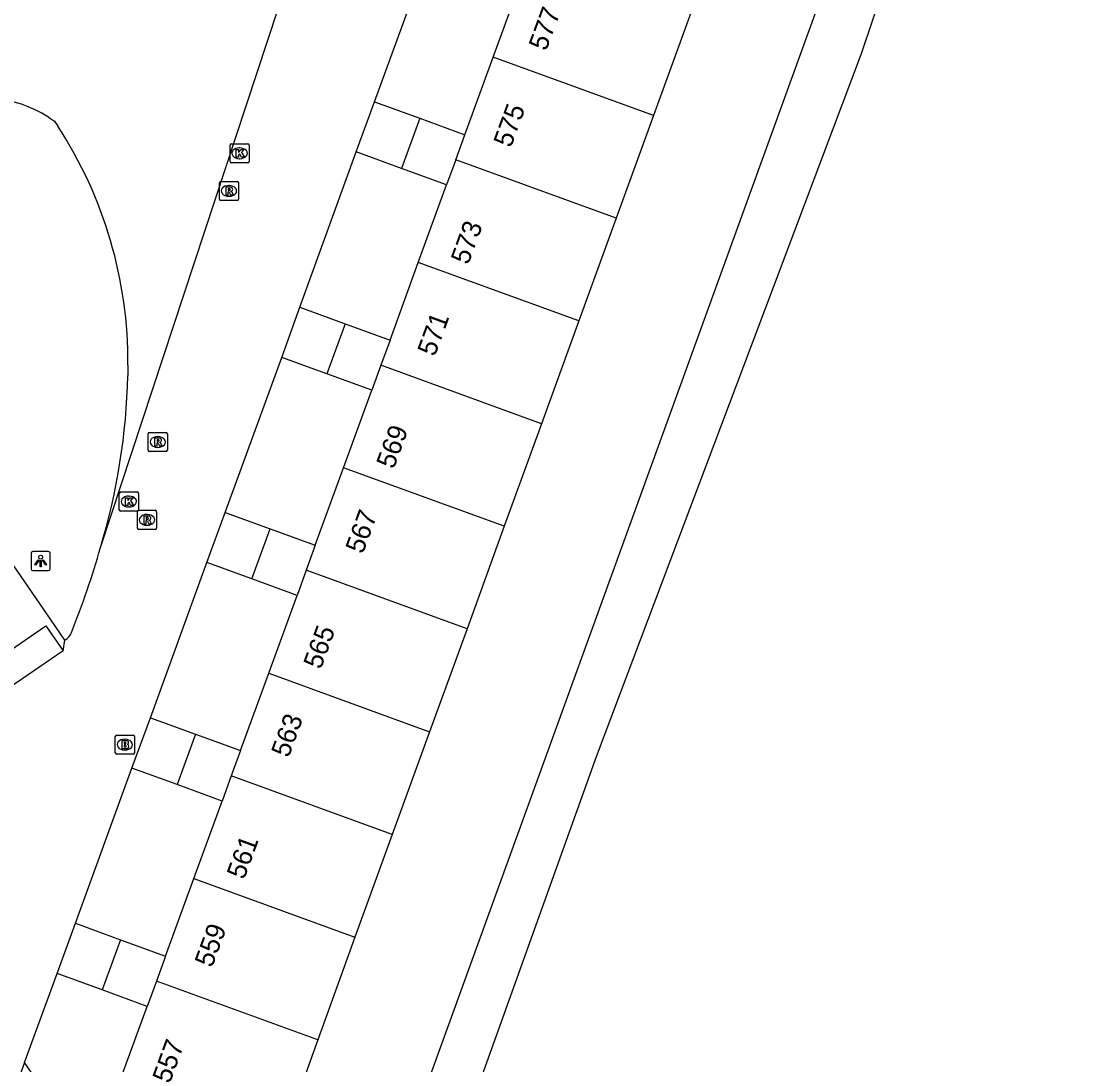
# Model space of a CAD drawing. Extents: x 155275 to 156263, y 382654 to 383635.
# Drawn here: x 155787.6 to 155842.7, y 383458.9 to 383513.4 of the extents above; entities that cross this region are included whole.
import ezdxf

# ---------------------------------------------------------------- set-up
doc = ezdxf.new("R2010")
doc.units = 0
for name, color, linetype in [('IMGEO_Brandkraan', 7, 'Continuous'), ('IMGEO_Erf', 7, 'Continuous'), ('IMGEO_Groenvoorziening', 7, 'Continuous'), ('IMGEO_Kolk', 7, 'Continuous'), ('IMGEO_Lichtpunt', 7, 'Continuous'), ('IMGEO_Meer_plas_ven_vijver', 7, 'Continuous'), ('IMGEO_Pand', 7, 'Continuous'), ('IMGEO_Pand_nummerreeks', 7, 'Continuous'), ('IMGEO_Rijbaan_lokaal_open', 7, 'Continuous'), ('IMGEO_Rioolput', 7, 'Continuous')]:
    doc.layers.add(name, color=color, linetype=linetype)

msp = doc.modelspace()

# ---------------------------------------------------------------- linework, layer by layer
at = {"layer": 'IMGEO_Brandkraan'}
for p, q in [((155792.473, 383475.2), (155792.473, 383476.052)), ((155792.548, 383476.126), (155793.4, 383476.126)), ((155793.474, 383476.052), (155793.474, 383475.2)), ((155792.961, 383475.906), (155792.986, 383475.906)), ((155793.4, 383475.126), (155792.548, 383475.126)), ((155792.984, 383475.346), (155792.959, 383475.346))]:
    msp.add_line(p, q, dxfattribs=at)
for points in [[(155792.473, 383475.2), (155792.473, 383476.052)], [(155792.548, 383476.126), (155793.4, 383476.126)], [(155793.474, 383476.052), (155793.474, 383475.2)], [(155792.821, 383475.826), (155792.821, 383475.426), (155793.034, 383475.426)], [(155793.052, 383475.826), (155792.821, 383475.826)], [(155793, 383475.745), (155792.946, 383475.745), (155792.946, 383475.669)], [(155792.946, 383475.669), (155792.999, 383475.669)], [(155793.008, 383475.593), (155792.946, 383475.593), (155792.946, 383475.512)], [(155792.946, 383475.512), (155793.008, 383475.512)], [(155793.4, 383475.126), (155792.548, 383475.126)]]:
    msp.add_lwpolyline(points, dxfattribs=at)
for centre, radius, start, end in [((155792.55, 383476.05), 0.0765, 91.552, 178.448), ((155792.55, 383476.05), 0.0765, 91.552, 178.448), ((155793.398, 383476.05), 0.0765, 1.552, 88.448), ((155793.398, 383476.05), 0.0765, 1.552, 88.448), ((155793.001, 383475.707), 0.0379, 267.8285, 90.9355), ((155793.009, 383475.552), 0.0404, 269.8759, 90.5077), ((155793.056, 383475.681), 0.145, 59.4692, 91.5367), ((155793.081, 383475.728), 0.0922, 285.5137, 58.1501), ((155793.086, 383475.536), 0.105, 301.3115, 78.989), ((155792.55, 383475.202), 0.0765, 181.552, 268.448), ((155792.55, 383475.202), 0.0765, 181.552, 268.448), ((155793.04, 383475.677), 0.251, 268.6676, 293.5347), ((155793.398, 383475.202), 0.0765, 271.552, 358.448), ((155793.398, 383475.202), 0.0765, 271.552, 358.448)]:
    msp.add_arc(centre, radius, start, end, dxfattribs=at)
for centre, major_axis, ratio, start_param, end_param in [((155792.96, 383475.626), (-0.387, 0.002), 0.722429, 4.712389, 7.853982), ((155792.985, 383475.626), (-0.39, 0.002), 0.717154, 1.570796, 4.712389)]:
    msp.add_ellipse(centre, major_axis=major_axis, ratio=ratio, start_param=start_param, end_param=end_param, dxfattribs=at)
at = {"layer": 'IMGEO_Erf'}
msp.add_lwpolyline([(155834.138, 383528.04), (155802.128, 383439.717), (155802.044, 383439.848)], dxfattribs=at)
at = {"layer": 'IMGEO_Groenvoorziening'}
msp.add_lwpolyline([(155800.366, 383442.462), (155799.563, 383441.901), (155787.734, 383459.039)], dxfattribs=at)
at = {"layer": 'IMGEO_Kolk'}
for p, q in [((155798.459, 383506.048), (155798.459, 383506.9)), ((155798.534, 383506.974), (155799.386, 383506.974)), ((155799.46, 383506.9), (155799.46, 383506.048)), ((155798.947, 383506.754), (155798.972, 383506.754)), ((155799.386, 383505.974), (155798.534, 383505.974)), ((155798.97, 383506.194), (155798.945, 383506.194)), ((155792.684, 383487.884), (155792.684, 383488.736)), ((155792.759, 383488.81), (155793.611, 383488.81)), ((155793.685, 383488.736), (155793.685, 383487.884)), ((155793.172, 383488.59), (155793.197, 383488.59)), ((155793.611, 383487.81), (155792.759, 383487.81)), ((155793.195, 383488.03), (155793.17, 383488.03))]:
    msp.add_line(p, q, dxfattribs=at)
for points in [[(155798.459, 383506.048), (155798.459, 383506.9)], [(155798.534, 383506.974), (155799.386, 383506.974)], [(155799.46, 383506.9), (155799.46, 383506.048)], [(155798.78, 383506.674), (155798.903, 383506.674), (155798.903, 383506.523), (155799.033, 383506.674), (155799.197, 383506.674), (155799.051, 383506.523), (155799.204, 383506.274), (155799.052, 383506.274), (155798.967, 383506.438), (155798.903, 383506.371), (155798.903, 383506.274), (155798.78, 383506.274), (155798.78, 383506.674)], [(155799.386, 383505.974), (155798.534, 383505.974)], [(155792.684, 383487.884), (155792.684, 383488.736)], [(155792.759, 383488.81), (155793.611, 383488.81)], [(155793.685, 383488.736), (155793.685, 383487.884)], [(155793.005, 383488.51), (155793.128, 383488.51), (155793.128, 383488.359), (155793.258, 383488.51), (155793.422, 383488.51), (155793.276, 383488.359), (155793.429, 383488.11), (155793.277, 383488.11), (155793.192, 383488.274), (155793.128, 383488.207), (155793.128, 383488.11), (155793.005, 383488.11), (155793.005, 383488.51)], [(155793.611, 383487.81), (155792.759, 383487.81)]]:
    msp.add_lwpolyline(points, dxfattribs=at)
for centre, start, end in [((155798.536, 383506.898), 91.552, 178.448), ((155798.536, 383506.898), 91.552, 178.448), ((155799.384, 383506.898), 1.552, 88.448), ((155799.384, 383506.898), 1.552, 88.448), ((155798.536, 383506.05), 181.552, 268.448), ((155798.536, 383506.05), 181.552, 268.448), ((155799.384, 383506.05), 271.552, 358.448), ((155799.384, 383506.05), 271.552, 358.448), ((155792.761, 383488.734), 91.552, 178.448), ((155792.761, 383488.734), 91.552, 178.448), ((155793.609, 383488.734), 1.552, 88.448), ((155793.609, 383488.734), 1.552, 88.448), ((155792.761, 383487.886), 181.552, 268.448), ((155792.761, 383487.886), 181.552, 268.448), ((155793.609, 383487.886), 271.552, 358.448), ((155793.609, 383487.886), 271.552, 358.448)]:
    msp.add_arc(centre, 0.0765, start, end, dxfattribs=at)
for centre, major_axis, ratio, start_param, end_param in [((155798.946, 383506.474), (-0.387, 0.002), 0.722429, 4.712389, 7.853982), ((155798.971, 383506.474), (-0.39, 0.002), 0.717154, 1.570796, 4.712389), ((155793.171, 383488.31), (-0.387, 0.002), 0.722429, 4.712389, 7.853982), ((155793.196, 383488.31), (-0.39, 0.002), 0.717154, 1.570796, 4.712389)]:
    msp.add_ellipse(centre, major_axis=major_axis, ratio=ratio, start_param=start_param, end_param=end_param, dxfattribs=at)
at = {"layer": 'IMGEO_Lichtpunt'}
for p, q in [((155788.086, 383485.608), (155788.086, 383484.801)), ((155788.086, 383485.608), (155788.086, 383484.801)), ((155788.988, 383485.703), (155788.18, 383485.703)), ((155788.988, 383485.703), (155788.18, 383485.703)), ((155789.082, 383484.801), (155789.082, 383485.608)), ((155789.082, 383484.801), (155789.082, 383485.608)), ((155788.18, 383484.707), (155788.988, 383484.707)), ((155788.18, 383484.707), (155788.988, 383484.707))]:
    msp.add_line(p, q, dxfattribs=at)
for points in [[(155788.46, 383485.272), (155788.499, 383485.244), (155788.311, 383484.982), (155788.273, 383485.009), (155788.46, 383485.272)], [(155788.562, 383485.224), (155788.609, 383485.224), (155788.609, 383484.902), (155788.562, 383484.902), (155788.562, 383485.224)], [(155788.672, 383485.244), (155788.71, 383485.271), (155788.897, 383485.009), (155788.858, 383484.981), (155788.672, 383485.244)]]:
    msp.add_lwpolyline(points, dxfattribs=at)
msp.add_circle((155788.585, 383485.406), 0.0994, dxfattribs=at)
for centre, start, end in [((155788.18, 383485.608), 90, 180), ((155788.18, 383485.608), 90, 180), ((155788.988, 383485.608), 0, 90), ((155788.988, 383485.608), 0, 90), ((155788.18, 383484.801), 180, 270), ((155788.18, 383484.801), 180, 270), ((155788.988, 383484.801), 270, 0), ((155788.988, 383484.801), 270, 360)]:
    msp.add_arc(centre, 0.0946, start, end, dxfattribs=at)
at = {"layer": 'IMGEO_Meer_plas_ven_vijver'}
msp.add_lwpolyline([(155801.722, 383438.959), (155801.973, 383438.955), (155802.639, 383439.172), (155803.541, 383439.534), (155804.583, 383440.594), (155809.395, 383452.096), (155810.94, 383456.516), (155817.567, 383475.003), (155826.387, 383498.439), (155831.377, 383511.689), (155832.532, 383515.106), (155833.021, 383516.146), (155833.72, 383517.195), (155834.455, 383518.079), (155835.622, 383518.636), (155836.89, 383519.063), (155838.457, 383519.394), (155840.158, 383519.527), (155841.365, 383519.524), (155842.905, 383519.259)], dxfattribs=at)
at = {"layer": 'IMGEO_Pand'}
for points in [[(155812.176, 383511.484), (155813.653, 383515.539)], [(155822.492, 383513.799), (155820.545, 383508.442)], [(155810.703, 383507.44), (155812.176, 383511.484)], [(155820.545, 383508.442), (155812.176, 383511.484)], [(155805.033, 383506.551), (155805.986, 383509.162)], [(155805.986, 383509.162), (155808.346, 383508.301)], [(155808.346, 383508.301), (155807.393, 383505.69)], [(155808.346, 383508.301), (155810.703, 383507.44)], [(155820.545, 383508.442), (155818.599, 383503.086)], [(155810.228, 383506.134), (155810.703, 383507.44)], [(155807.393, 383505.69), (155805.033, 383506.551)], [(155810.228, 383506.134), (155809.752, 383504.828)], [(155818.599, 383503.086), (155810.228, 383506.134)], [(155809.752, 383504.828), (155807.393, 383505.69)], [(155808.275, 383500.772), (155809.752, 383504.828)], [(155818.599, 383503.086), (155816.651, 383497.727)], [(155806.802, 383496.728), (155808.275, 383500.772)], [(155816.651, 383497.727), (155808.275, 383500.772)], [(155801.152, 383495.828), (155802.104, 383498.44)], [(155802.104, 383498.44), (155804.453, 383497.584)], [(155804.453, 383497.584), (155803.501, 383494.972)], [(155804.453, 383497.584), (155806.802, 383496.728)], [(155816.651, 383497.727), (155814.704, 383492.369)], [(155806.802, 383496.728), (155806.326, 383495.422)], [(155803.501, 383494.972), (155801.152, 383495.828)], [(155806.326, 383495.422), (155805.85, 383494.116)], [(155814.704, 383492.369), (155806.326, 383495.422)], [(155805.85, 383494.116), (155803.501, 383494.972)], [(155804.374, 383490.065), (155805.85, 383494.116)], [(155814.704, 383492.369), (155812.759, 383487.018)], [(155802.903, 383486.026), (155804.374, 383490.065)], [(155812.759, 383487.018), (155804.374, 383490.065)], [(155797.254, 383485.125), (155798.205, 383487.738)], [(155798.205, 383487.738), (155800.554, 383486.882)], [(155799.603, 383484.27), (155800.554, 383486.882)], [(155800.554, 383486.882), (155802.903, 383486.026)], [(155812.759, 383487.018), (155810.814, 383481.667)], [(155802.903, 383486.026), (155802.428, 383484.72)], [(155799.603, 383484.27), (155797.254, 383485.125)], [(155802.428, 383484.72), (155801.952, 383483.414)], [(155810.814, 383481.667), (155802.428, 383484.72)], [(155801.952, 383483.414), (155799.603, 383484.27)], [(155800.473, 383479.353), (155801.952, 383483.414)], [(155810.814, 383481.667), (155808.865, 383476.303)], [(155799.002, 383475.315), (155800.473, 383479.353)], [(155800.473, 383479.353), (155808.865, 383476.303)], [(155793.345, 383474.395), (155794.304, 383477.026)], [(155794.304, 383477.026), (155796.652, 383476.171)], [(155796.652, 383476.171), (155795.694, 383473.54)], [(155796.652, 383476.171), (155799.002, 383475.315)], [(155808.865, 383476.303), (155806.916, 383470.94)], [(155799.002, 383475.315), (155798.523, 383474)], [(155795.694, 383473.54), (155793.345, 383474.395)], [(155798.523, 383474), (155798.043, 383472.684)], [(155806.916, 383470.94), (155798.523, 383474)], [(155798.043, 383472.684), (155795.694, 383473.54)], [(155796.568, 383468.636), (155798.043, 383472.684)], [(155806.916, 383470.94), (155804.969, 383465.583)], [(155795.096, 383464.594), (155796.568, 383468.636)], [(155796.568, 383468.636), (155804.969, 383465.583)], [(155789.443, 383463.684), (155790.398, 383466.305)], [(155790.398, 383466.305), (155792.748, 383465.449)], [(155804.969, 383465.583), (155804.794, 383465.102), (155803.038, 383460.22)], [(155792.748, 383465.449), (155791.792, 383462.828)], [(155792.748, 383465.449), (155795.096, 383464.594)], [(155795.096, 383464.594), (155794.619, 383463.283)], [(155791.792, 383462.828), (155789.443, 383463.684)], [(155794.142, 383461.972), (155791.792, 383462.828)], [(155794.619, 383463.283), (155794.142, 383461.972)], [(155803.038, 383460.22), (155794.619, 383463.283)], [(155792.668, 383457.927), (155794.142, 383461.972)], [(155803.038, 383460.22), (155801.109, 383454.856)]]:
    msp.add_lwpolyline(points, dxfattribs=at)
at = {"layer": 'IMGEO_Rijbaan_lokaal_open'}
for points in [[(155805.986, 383509.162), (155808.943, 383517.259)], [(155791.706, 383485.914), (155801.501, 383515.661)], [(155788.985, 383508.361), (155789.094, 383508.292), (155789.202, 383508.22), (155789.308, 383508.147), (155789.366, 383508.061), (155789.423, 383507.975), (155789.48, 383507.888)], [(155802.104, 383498.44), (155805.033, 383506.551)], [(155793.136, 383495.42), (155793.134, 383495.237), (155793.131, 383495.053), (155793.126, 383494.87)], [(155798.205, 383487.738), (155801.152, 383495.828)], [(155789.846, 383481.079), (155789.132, 383482.119), (155781.607, 383493.059)], [(155794.304, 383477.026), (155797.254, 383485.125)], [(155785.714, 383479.674), (155788.861, 383481.817), (155789.751, 383480.519)], [(155789.751, 383480.519), (155789.846, 383481.079)], [(155789.751, 383480.519), (155786.61, 383478.372)], [(155790.398, 383466.305), (155793.345, 383474.395)], [(155787.734, 383459.039), (155789.443, 383463.684)], [(155787.734, 383459.039), (155782.858, 383445.59)]]:
    msp.add_lwpolyline(points, dxfattribs=at)
for centre, radius, start, end in [((155785.312, 383502.466), 6.946, 58.0794, 160.5007), ((155770.607, 383495.584), 22.53, 359.5837, 33.1018), ((155759.436, 383495.621), 33.699, 343.2583, 358.7228), ((155749.822, 383497.758), 43.526, 338.0455, 344.2098), ((155789.481, 383481.741), 0.756, 298.8989, 340.2247)]:
    msp.add_arc(centre, radius, start, end, dxfattribs=at)
at = {"layer": 'IMGEO_Rioolput'}
for p, q in [((155797.901, 383504.084), (155797.901, 383504.936)), ((155797.976, 383505.01), (155798.828, 383505.01)), ((155798.389, 383504.79), (155798.414, 383504.79)), ((155798.902, 383504.936), (155798.902, 383504.084)), ((155798.412, 383504.23), (155798.387, 383504.23)), ((155798.828, 383504.01), (155797.976, 383504.01)), ((155794.191, 383490.988), (155794.191, 383491.84)), ((155794.266, 383491.914), (155795.118, 383491.914)), ((155794.679, 383491.694), (155794.704, 383491.694)), ((155795.192, 383491.84), (155795.192, 383490.988)), ((155795.118, 383490.914), (155794.266, 383490.914)), ((155794.702, 383491.134), (155794.677, 383491.134)), ((155793.629, 383486.927), (155793.629, 383487.779)), ((155793.704, 383487.853), (155794.556, 383487.853)), ((155794.117, 383487.633), (155794.142, 383487.633)), ((155794.63, 383487.779), (155794.63, 383486.927)), ((155794.14, 383487.073), (155794.115, 383487.073)), ((155794.556, 383486.853), (155793.704, 383486.853))]:
    msp.add_line(p, q, dxfattribs=at)
for points in [[(155797.901, 383504.084), (155797.901, 383504.936)], [(155797.976, 383505.01), (155798.828, 383505.01)], [(155798.49, 383504.708), (155798.238, 383504.71), (155798.238, 383504.31)], [(155798.902, 383504.936), (155798.902, 383504.084)], [(155798.238, 383504.31), (155798.362, 383504.31), (155798.362, 383504.472), (155798.373, 383504.472)], [(155798.416, 383504.629), (155798.362, 383504.629), (155798.362, 383504.548)], [(155798.362, 383504.548), (155798.414, 383504.548)], [(155798.42, 383504.443), (155798.491, 383504.31), (155798.631, 383504.31), (155798.566, 383504.436)], [(155798.828, 383504.01), (155797.976, 383504.01)], [(155794.191, 383490.988), (155794.191, 383491.84)], [(155794.266, 383491.914), (155795.118, 383491.914)], [(155794.78, 383491.612), (155794.528, 383491.614), (155794.528, 383491.214)], [(155794.706, 383491.533), (155794.652, 383491.533), (155794.652, 383491.452)], [(155794.652, 383491.452), (155794.704, 383491.452)], [(155795.192, 383491.84), (155795.192, 383490.988)], [(155795.118, 383490.914), (155794.266, 383490.914)], [(155794.528, 383491.214), (155794.652, 383491.214), (155794.652, 383491.376), (155794.663, 383491.376)], [(155794.71, 383491.347), (155794.781, 383491.214), (155794.921, 383491.214), (155794.856, 383491.34)], [(155793.629, 383486.927), (155793.629, 383487.779)], [(155793.704, 383487.853), (155794.556, 383487.853)], [(155794.63, 383487.779), (155794.63, 383486.927)], [(155794.218, 383487.551), (155793.966, 383487.553), (155793.966, 383487.153)], [(155793.966, 383487.153), (155794.09, 383487.153), (155794.09, 383487.315), (155794.101, 383487.315)], [(155794.144, 383487.472), (155794.09, 383487.472), (155794.09, 383487.391)], [(155794.09, 383487.391), (155794.142, 383487.391)], [(155794.148, 383487.286), (155794.219, 383487.153), (155794.359, 383487.153), (155794.294, 383487.279)], [(155794.556, 383486.853), (155793.704, 383486.853)]]:
    msp.add_lwpolyline(points, dxfattribs=at)
for centre, radius, start, end in [((155797.978, 383504.934), 0.0765, 91.552, 178.448), ((155797.978, 383504.934), 0.0765, 91.552, 178.448), ((155798.489, 383504.598), 0.109, 350.3612, 89.416), ((155798.826, 383504.934), 0.0765, 1.552, 88.448), ((155798.826, 383504.934), 0.0765, 1.552, 88.448), ((155798.372, 383504.419), 0.0533, 26.0293, 88.6989), ((155798.398, 383504.737), 0.19, 274.7715, 282.9687), ((155798.422, 383504.533), 0.0964, 77.0061, 93.1865), ((155798.436, 383504.59), 0.0378, 276.6634, 79.6772), ((155798.487, 383504.598), 0.112, 277.5842, 350.9817), ((155798.471, 383504.383), 0.108, 29.5134, 73.7905), ((155797.978, 383504.086), 0.0765, 181.552, 268.448), ((155797.978, 383504.086), 0.0765, 181.552, 268.448), ((155798.826, 383504.086), 0.0765, 271.552, 358.448), ((155798.826, 383504.086), 0.0765, 271.552, 358.448), ((155794.268, 383491.838), 0.0765, 91.552, 178.448), ((155794.268, 383491.838), 0.0765, 91.552, 178.448), ((155794.688, 383491.641), 0.19, 274.7715, 282.9687), ((155794.712, 383491.437), 0.0964, 77.0061, 93.1865), ((155794.726, 383491.494), 0.0378, 276.6634, 79.6772), ((155794.779, 383491.502), 0.109, 350.3612, 89.416), ((155794.777, 383491.502), 0.112, 277.5842, 350.9817), ((155795.116, 383491.838), 0.0765, 1.552, 88.448), ((155795.116, 383491.838), 0.0765, 1.552, 88.448), ((155794.268, 383490.99), 0.0765, 181.552, 268.448), ((155794.268, 383490.99), 0.0765, 181.552, 268.448), ((155794.662, 383491.323), 0.0533, 26.0293, 88.6989), ((155794.761, 383491.287), 0.108, 29.5134, 73.7905), ((155795.116, 383490.99), 0.0765, 271.552, 358.448), ((155795.116, 383490.99), 0.0765, 271.552, 358.448), ((155793.706, 383487.777), 0.0765, 91.552, 178.448), ((155793.706, 383487.777), 0.0765, 91.552, 178.448), ((155794.554, 383487.777), 0.0765, 1.552, 88.448), ((155794.554, 383487.777), 0.0765, 1.552, 88.448), ((155794.1, 383487.262), 0.0533, 26.0293, 88.6989), ((155794.126, 383487.58), 0.19, 274.7715, 282.9687), ((155794.15, 383487.376), 0.0964, 77.0061, 93.1865), ((155794.164, 383487.433), 0.0378, 276.6634, 79.6772), ((155794.217, 383487.441), 0.109, 350.3612, 89.416), ((155794.215, 383487.441), 0.112, 277.5842, 350.9817), ((155794.199, 383487.226), 0.108, 29.5134, 73.7905), ((155793.706, 383486.929), 0.0765, 181.552, 268.448), ((155793.706, 383486.929), 0.0765, 181.552, 268.448), ((155794.554, 383486.929), 0.0765, 271.552, 358.448), ((155794.554, 383486.929), 0.0765, 271.552, 358.448)]:
    msp.add_arc(centre, radius, start, end, dxfattribs=at)
for centre, major_axis, ratio, start_param, end_param in [((155798.388, 383504.51), (-0.387, 0.002), 0.722429, 4.712389, 7.853982), ((155798.413, 383504.51), (-0.39, 0.002), 0.717154, 1.570796, 4.712389), ((155794.678, 383491.414), (-0.387, 0.002), 0.722429, 4.712389, 7.853982), ((155794.703, 383491.414), (-0.39, 0.002), 0.717154, 1.570796, 4.712389), ((155794.116, 383487.353), (-0.387, 0.002), 0.722429, 4.712389, 7.853982), ((155794.141, 383487.353), (-0.39, 0.002), 0.717154, 1.570796, 4.712389)]:
    msp.add_ellipse(centre, major_axis=major_axis, ratio=ratio, start_param=start_param, end_param=end_param, dxfattribs=at)

# ---------------------------------------------------------------- texts
at = {"layer": 'IMGEO_Pand_nummerreeks'}
for s, rotation, p in [('577', 69.7863, (155814.936, 383511.769)), ('575', 69.7863, (155813.099, 383506.725)), ('573', 69.792, (155810.875, 383500.619)), ('571', 69.7863, (155809.133, 383495.836)), ('569', 69.7805, (155806.992, 383489.961)), ('567', 69.792, (155805.381, 383485.536)), ('565', 69.792, (155803.187, 383479.512)), ('563', 69.7863, (155801.508, 383474.903)), ('561', 69.7805, (155799.192, 383468.549)), ('559', 69.792, (155797.519, 383463.955)), ('557', 69.7805, (155795.316, 383457.907))]:
    msp.add_text(s, height=1, rotation=rotation, dxfattribs=at).set_placement(p)

doc.saveas('drawing.dxf')
